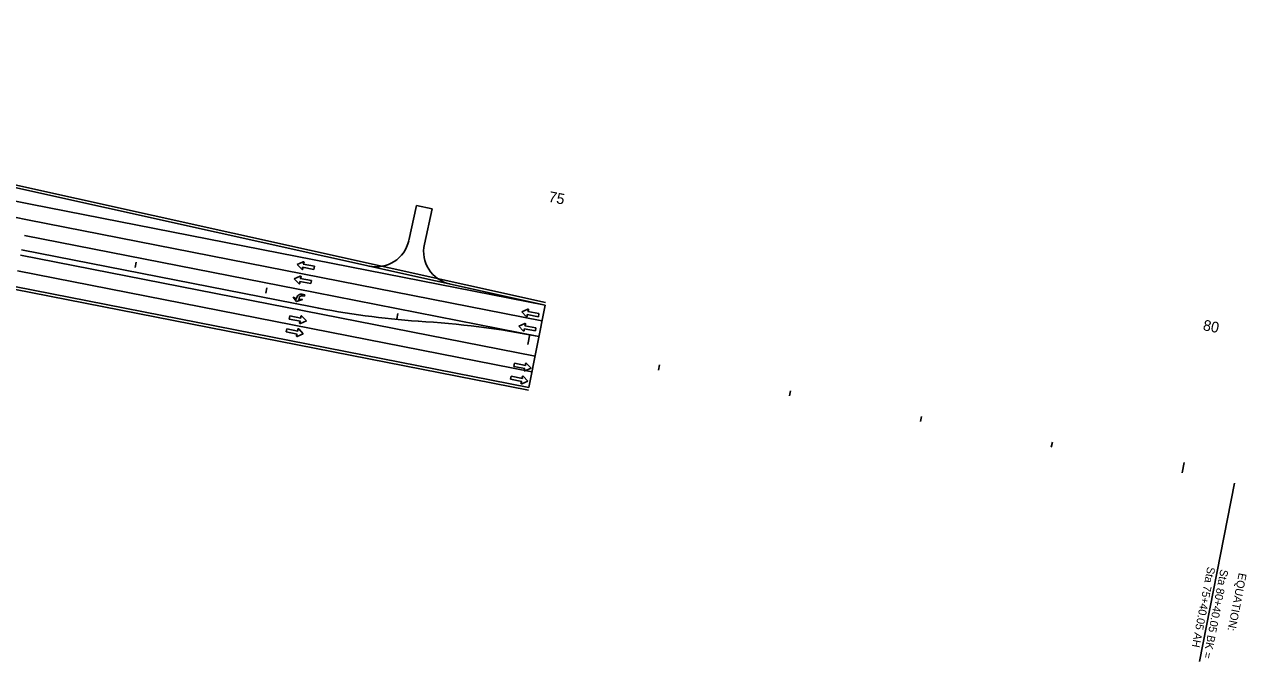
# Model space of a CAD drawing. Extents: x 1936748 to 1944587, y 778949 to 784066.
# Drawn here: x 1943671 to 1944587, y 779663 to 780140 of the extents above; entities that cross this region are included whole.
import ezdxf

# ---------------------------------------------------------------- set-up
doc = ezdxf.new("R2010")
doc.units = 0
for name, color, linetype in [('Default', 7, 'Continuous'), ('RD_HC_Data', 7, 'Continuous'), ('RD_HC_Data_Tic', 7, 'Continuous'), ('RD_HC_TX_Sta50', 7, 'Continuous'), ('RD_PD_ALT1_LnLine', 7, 'Continuous'), ('RD_PD_ALT3_LnLine', 7, 'Continuous'), ('RD_PD_Driveway', 7, 'Continuous'), ('RD_PD_Final_TrvlWay', 7, 'Continuous'), ('RD_PD_PaveShd', 7, 'Continuous')]:
    doc.layers.add(name, color=color, linetype=linetype)

msp = doc.modelspace()

# ---------------------------------------------------------------- linework, layer by layer
at = {"layer": 'Default'}
for p, q in [((1943879.71, 779962.32), (1943875.15, 779960.33)), ((1943875.15, 779960.33), (1943878.59, 779956.73)), ((1943879.33, 779957.07), (1943879.27, 779958.31)), ((1943879.27, 779958.31), (1943887.62, 779956.62)), ((1943879.71, 779962.32), (1943879.71, 779962.32)), ((1943879.74, 779960.6), (1943880.27, 779961.75)), ((1943888.09, 779958.92), (1943879.74, 779960.6)), ((1943887.62, 779956.62), (1943888.09, 779958.92)), ((1943877.49, 779951.6), (1943872.93, 779949.61)), ((1943872.93, 779949.61), (1943876.36, 779946.01)), ((1943877.1, 779946.35), (1943877.05, 779947.59)), ((1943877.05, 779947.59), (1943885.4, 779945.9)), ((1943877.49, 779951.6), (1943877.49, 779951.6)), ((1943877.51, 779949.88), (1943878.05, 779951.03)), ((1943885.86, 779948.2), (1943877.51, 779949.88)), ((1943885.4, 779945.9), (1943885.86, 779948.2)), ((1943879.32, 779936.8), (1943880.65, 779936.48)), ((1943869.65, 779921.69), (1943869.18, 779919.4)), ((1943869.18, 779919.4), (1943877.53, 779917.71)), ((1943878, 779920.01), (1943869.65, 779921.69)), ((1943877.94, 779921.24), (1943878, 779920.01)), ((1943882.12, 779917.98), (1943878.68, 779921.58)), ((1944048.05, 779926.86), (1944043.49, 779924.87)), ((1944043.49, 779924.87), (1944046.93, 779921.27)), ((1944047.67, 779921.61), (1944047.61, 779922.85)), ((1944047.61, 779922.85), (1944055.96, 779921.16)), ((1944048.05, 779926.86), (1944048.05, 779926.86)), ((1944048.07, 779925.14), (1944048.61, 779926.29)), ((1944056.43, 779923.46), (1944048.07, 779925.14)), ((1944055.96, 779921.16), (1944056.43, 779923.46)), ((1943867.28, 779912.05), (1943866.81, 779909.76)), ((1943866.81, 779909.76), (1943875.16, 779908.07)), ((1943875.63, 779910.37), (1943867.28, 779912.05)), ((1943875.57, 779911.6), (1943875.63, 779910.37)), ((1943879.75, 779908.34), (1943876.31, 779911.94)), ((1943877.53, 779917.71), (1943877, 779916.57)), ((1943877.55, 779916), (1943882.12, 779917.98)), ((1943877.55, 779916), (1943877.55, 779916)), ((1944045.83, 779916.14), (1944041.27, 779914.15)), ((1944041.27, 779914.15), (1944044.7, 779910.55)), ((1944045.44, 779910.89), (1944045.39, 779912.13)), ((1944045.39, 779912.13), (1944053.74, 779910.44)), ((1944045.83, 779916.14), (1944045.83, 779916.14)), ((1944045.85, 779914.42), (1944046.39, 779915.57)), ((1944054.2, 779912.74), (1944045.85, 779914.42)), ((1944053.74, 779910.44), (1944054.2, 779912.74)), ((1943875.16, 779908.07), (1943874.63, 779906.93)), ((1943875.19, 779906.36), (1943879.75, 779908.34)), ((1943875.19, 779906.36), (1943875.19, 779906.36)), ((1944037.98, 779886.24), (1944037.52, 779883.94)), ((1944037.52, 779883.94), (1944045.87, 779882.26)), ((1944046.34, 779884.55), (1944037.98, 779886.24)), ((1944045.87, 779882.26), (1944045.34, 779881.11)), ((1944045.89, 779880.54), (1944050.46, 779882.52)), ((1944046.28, 779885.79), (1944046.34, 779884.55)), ((1944050.46, 779882.52), (1944047.02, 779886.13)), ((1944035.61, 779876.59), (1944035.15, 779874.3)), ((1944035.15, 779874.3), (1944043.5, 779872.62)), ((1944043.97, 779874.91), (1944035.61, 779876.59)), ((1944043.91, 779876.14), (1944043.97, 779874.91)), ((1944048.09, 779872.88), (1944044.65, 779876.48)), ((1944045.89, 779880.54), (1944045.89, 779880.54)), ((1944043.5, 779872.62), (1944042.97, 779871.47)), ((1944043.52, 779870.9), (1944048.09, 779872.88)), ((1944043.52, 779870.9), (1944043.52, 779870.9))]:
    msp.add_line(p, q, dxfattribs=at)
for points in [[(1943880.65, 779936.48), (1943880.88, 779937.45), (1943878.89, 779937.93)], [(1943874.93, 779935.51), (1943874.68, 779934.49), (1943872.25, 779935.76), (1943874.54, 779932.47), (1943879.05, 779934.12), (1943876.3, 779934.1), (1943876.55, 779935.11)]]:
    msp.add_lwpolyline(points, dxfattribs=at)
for centre, radius, start, end in [((1943878.9, 779957.02), 0.443, 223.51206, 3.97518), ((1943879.9, 779961.93), 0.443, 333.30097, 113.78719), ((1943876.68, 779946.3), 0.443, 223.51206, 3.97518), ((1943877.67, 779951.21), 0.443, 333.30097, 113.78719), ((1943878.12, 779934.74), 3.28, 76.47643, 166.47643), ((1943878.78, 779934.57), 2.3, 76.47643, 166.47643), ((1943878.37, 779921.29), 0.443, 43.51206, 183.97518), ((1944047.24, 779921.56), 0.443, 223.51206, 3.97518), ((1944048.23, 779926.47), 0.443, 333.30097, 113.78719), ((1943876, 779911.65), 0.443, 43.51206, 183.97518), ((1943877.37, 779916.39), 0.443, 153.30097, 293.78719), ((1944045.02, 779910.84), 0.443, 223.51206, 3.97518), ((1944046.01, 779915.75), 0.443, 333.30097, 113.78719), ((1943875, 779906.74), 0.443, 153.30097, 293.78719), ((1944046.71, 779885.84), 0.443, 43.51206, 183.97518), ((1944044.34, 779876.2), 0.443, 43.51206, 183.97518), ((1944045.71, 779880.93), 0.443, 153.30097, 293.78719), ((1944043.34, 779871.29), 0.443, 153.30097, 293.78719)]:
    msp.add_arc(centre, radius, start, end, dxfattribs=at)
at = {"layer": 'RD_HC_Data'}
msp.add_line((1944577.95, 779796.33), (1944551.75, 779662.72), dxfattribs=at)
at = {"layer": 'RD_HC_Data_Tic'}
for p, q in [((1943753.62, 779958.04), (1943754.39, 779961.96)), ((1943851.75, 779938.79), (1943852.52, 779942.71)), ((1943949.88, 779919.54), (1943950.65, 779923.46)), ((1944048.01, 779900.29), (1944049.55, 779908.14)), ((1944146.14, 779881.04), (1944146.91, 779884.96)), ((1944244.27, 779861.79), (1944245.04, 779865.71)), ((1944342.4, 779842.54), (1944343.17, 779846.46)), ((1944440.53, 779823.29), (1944441.3, 779827.21)), ((1944538.65, 779804.04), (1944540.19, 779811.89))]:
    msp.add_line(p, q, dxfattribs=at)
at = {"layer": 'RD_PD_ALT1_LnLine'}
for p, q in [((1943675.31, 780005.5), (1944060.99, 779929.84)), ((1943673, 779993.72), (1944058.68, 779918.07)), ((1943670.69, 779981.95), (1943888.56, 779939.21)), ((1943665.49, 779955.45), (1944051.17, 779879.79)), ((1943888.56, 779939.21), (1944056.37, 779906.29))]:
    msp.add_line(p, q, dxfattribs=at)
for radius, start in [(7850.5, 254.290417), (7838.5, 257.388687)]:
    msp.add_arc((1945184.18, 787697.4), radius, start, 258.901557, dxfattribs=at)
at = {"layer": 'RD_PD_ALT3_LnLine'}
for p, q in [((1943667.8, 779967.23), (1944053.48, 779891.57)), ((1943668.57, 779971.15), (1943886.45, 779928.41))]:
    msp.add_line(p, q, dxfattribs=at)
for centre, start, end in [((1944015.42, 780585.88), 258.90156, 265.76894), ((1943927.39, 779248.82), 78.90156, 86.69789)]:
    msp.add_arc(centre, 670, start, end, dxfattribs=at)
at = {"layer": 'RD_PD_Driveway'}
msp.add_lwpolyline([(1943958.79, 779978.12), (1943964.63, 780004.45), (1943976.34, 780001.85), (1943970.5, 779975.52)], dxfattribs=at)
for centre, start, end in [((1943934.38, 779983.53), 257.4946, 347.4946), ((1943994.91, 779970.1), 167.4946, 257.4946)]:
    msp.add_arc(centre, 25, start, end, dxfattribs=at)
at = {"layer": 'RD_PD_Final_TrvlWay'}
for p, q in [((1943475.38, 780059.73), (1944060.99, 779929.84)), ((1943663.18, 779943.68), (1944048.86, 779868.02)), ((1944048.86, 779868.02), (1944060.99, 779929.84))]:
    msp.add_line(p, q, dxfattribs=at)
at = {"layer": 'RD_PD_PaveShd'}
for p, q in [((1943475.81, 780061.68), (1944061.42, 779931.79)), ((1943662.8, 779941.71), (1944048.47, 779866.06))]:
    msp.add_line(p, q, dxfattribs=at)

# ---------------------------------------------------------------- texts
at = {"layer": 'RD_HC_Data'}
for s, p in [('Sta 75+40.05 AH', (1944557.59, 779734.09)), ('Sta 80+40.05 BK = ', (1944567.41, 779732.16)), ('EQUATION:', (1944581.14, 779729.47))]:
    msp.add_text(s, height=6, rotation=258.90156, dxfattribs=at).set_placement(p)
at = {"layer": 'RD_HC_TX_Sta50'}
for s, p in [('75', (1944063.14, 780007.38)), ('80', (1944553.76, 779911.14))]:
    msp.add_text(s, height=8, rotation=348.90156, dxfattribs=at).set_placement(p)

doc.saveas('drawing.dxf')
